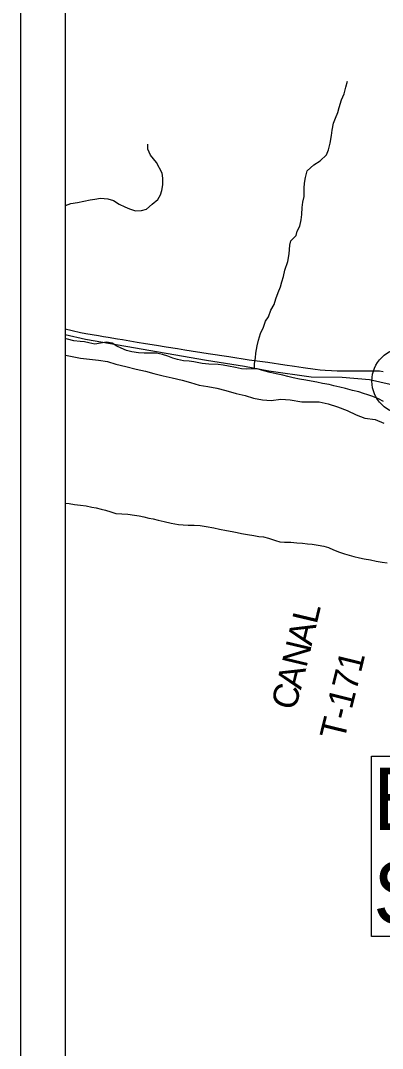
# Model space of a CAD drawing. Extents: x 0 to 34, y 0 to 22.
# Drawn here: x 2.214 to 3.024, y 17.472 to 19.77 of the extents above; entities that cross this region are included whole.
import ezdxf

# ---------------------------------------------------------------- set-up
doc = ezdxf.new("R2010")
doc.units = 0
for name, color, linetype in [('Default', 7, 'Continuous'), ('GM_X_Major_River', 7, 'Continuous'), ('GM_X_Minor_River', 7, 'Continuous'), ('GM_X_Rail_Line', 7, 'Continuous'), ('GM_X_Township_Road_Text', 7, 'Continuous'), ('GM_X_Unincorporated', 7, 'Continuous'), ('GM_X_US_Route', 7, 'Continuous'), ('SH_Cut_Line', 7, 'Continuous'), ('SH_Data', 7, 'Continuous'), ('SH_Text', 7, 'Continuous')]:
    doc.layers.add(name, color=color, linetype=linetype)

msp = doc.modelspace()

# ---------------------------------------------------------------- linework, layer by layer
at = {"layer": 'Default'}
msp.add_lwpolyline([(2.3142, 20.7876), (2.3142, 19.0219), (2.3186, 19.0209), (2.3482, 19.0152), (2.3686, 19.0125), (2.3884, 19.0102), (2.4084, 19.0072), (2.4274, 19.0019), (2.4494, 18.9966), (2.4732, 18.9901), (2.4937, 18.986), (2.5127, 18.981), (2.5335, 18.9753), (2.5532, 18.9712), (2.5756, 18.9658), (2.5945, 18.9605), (2.6138, 18.9548), (2.6328, 18.9514), (2.6532, 18.9476), (2.6733, 18.9427), (2.6968, 18.9359), (2.7165, 18.9317), (2.7355, 18.9252), (2.7556, 18.9215), (2.7749, 18.9203), (2.7961, 18.923), (2.817, 18.9218), (2.8431, 18.9173), (2.8632, 18.9177), (2.8825, 18.9173), (2.9026, 18.9127), (2.9231, 18.9063), (2.9447, 18.8979), (2.9651, 18.8884), (2.9841, 18.8809), (3.0072, 18.8782), (3.0269, 18.8695)], dxfattribs=at)
at = {"layer": 'GM_X_Major_River'}
for points in [[(2.6561, 19.0009), (2.6353, 19.0012), (2.6203, 19.003), (2.6022, 19.007), (2.5916, 19.0083), (2.5788, 19.0093), (2.5656, 19.0121), (2.5547, 19.0153), (2.5434, 19.0193), (2.5314, 19.0233), (2.5182, 19.0261), (2.5076, 19.0263), (2.4906, 19.0258), (2.4777, 19.0271), (2.4634, 19.0292), (2.451, 19.0321), (2.4393, 19.0372), (2.4296, 19.0419), (2.4191, 19.0485), (2.4067, 19.0509), (2.3934, 19.0485), (2.3805, 19.046), (2.3673, 19.0493), (2.3575, 19.0513), (2.3474, 19.0526), (2.3334, 19.0536), (2.3191, 19.0572), (2.3142, 19.0591)], [(3.0264, 18.918), (3.0148, 18.9238), (3.0024, 18.9289), (2.9907, 18.9333), (2.981, 18.9361), (2.9708, 18.94), (2.9569, 18.9429), (2.9414, 18.9473), (2.9283, 18.9502), (2.9151, 18.9534), (2.9049, 18.9558), (2.8894, 18.9587), (2.877, 18.9612), (2.8642, 18.9636), (2.8525, 18.9657), (2.8382, 18.9682), (2.8242, 18.9711), (2.8122, 18.9739), (2.8009, 18.9767), (2.7862, 18.9796), (2.7723, 18.9829), (2.7583, 18.9865), (2.7433, 18.9912), (2.7304, 18.9911), (2.7206, 18.9901), (2.7081, 18.9914), (2.695, 18.9943), (2.6791, 18.9968), (2.6678, 18.9992), (2.6561, 19.0009)], [(2.3142, 18.691), (2.3226, 18.6897), (2.3347, 18.688), (2.3482, 18.6866), (2.3611, 18.6846), (2.3739, 18.6821), (2.3837, 18.68), (2.3946, 18.6776), (2.4044, 18.6748), (2.4164, 18.6712), (2.4277, 18.668), (2.4409, 18.6667), (2.4545, 18.6665), (2.4692, 18.6643), (2.4798, 18.6623), (2.49, 18.6602), (2.5009, 18.6574), (2.5107, 18.6554), (2.522, 18.6529), (2.5355, 18.6497), (2.551, 18.6457), (2.5676, 18.6428), (2.5778, 18.6422), (2.5895, 18.6417), (2.6027, 18.6415), (2.6159, 18.6409), (2.6295, 18.6384), (2.6468, 18.6359), (2.6593, 18.633), (2.6747, 18.6298), (2.6879, 18.6273), (2.6984, 18.6252), (2.7082, 18.6232), (2.7218, 18.6207), (2.7358, 18.6182), (2.7475, 18.6165), (2.7576, 18.6152), (2.7689, 18.6128), (2.7844, 18.6073), (2.7945, 18.6041), (2.8047, 18.6039), (2.8191, 18.6033), (2.8319, 18.6024), (2.8451, 18.601), (2.8564, 18.6001), (2.8662, 18.5992), (2.8802, 18.5971), (2.8926, 18.5946), (2.9032, 18.5918), (2.9144, 18.5863), (2.9276, 18.5812), (2.9389, 18.5776), (2.9494, 18.5744), (2.9599, 18.5716), (2.9724, 18.5684), (2.9829, 18.5663), (2.9972, 18.5638), (3.0097, 18.5614), (3.0229, 18.5589), (3.0342, 18.5572)]]:
    msp.add_lwpolyline(points, dxfattribs=at)
at = {"layer": 'GM_X_Minor_River'}
for points in [[(2.7374, 18.9912), (2.7378, 19.0034), (2.7399, 19.0159), (2.7408, 19.0265), (2.7433, 19.0428), (2.7462, 19.0552), (2.751, 19.0703), (2.7573, 19.0846), (2.7624, 19.0978), (2.7686, 19.1076), (2.7742, 19.1223), (2.7812, 19.1351), (2.7856, 19.1476), (2.7907, 19.1615), (2.7955, 19.1747), (2.7987, 19.1853), (2.8023, 19.1974), (2.8055, 19.2117), (2.8119, 19.2314), (2.8152, 19.2484), (2.8163, 19.2673), (2.8191, 19.2771), (2.8307, 19.2891), (2.8331, 19.2989), (2.8393, 19.3098), (2.8418, 19.3242), (2.8435, 19.3359), (2.8442, 19.3515), (2.8455, 19.3636), (2.8484, 19.3761), (2.8487, 19.395), (2.8492, 19.406), (2.8517, 19.4189), (2.8554, 19.4336), (2.8704, 19.4471), (2.8845, 19.4563), (2.8987, 19.4698), (2.9027, 19.4807), (2.9067, 19.4954), (2.9097, 19.5132), (2.911, 19.5249), (2.9139, 19.5401), (2.9186, 19.5514), (2.9238, 19.5646), (2.927, 19.5752), (2.9325, 19.5925), (2.9381, 19.6057), (2.9421, 19.6212), (2.9453, 19.634)], [(2.3142, 19.356), (2.3151, 19.3563), (2.3265, 19.3606), (2.3414, 19.3634), (2.3558, 19.3659), (2.3702, 19.3687), (2.3805, 19.3708), (2.393, 19.3725), (2.4096, 19.3715), (2.422, 19.3675), (2.4351, 19.359), (2.4472, 19.3535), (2.4577, 19.3487), (2.4712, 19.3447), (2.4845, 19.3449), (2.4963, 19.3485), (2.5086, 19.3593), (2.5216, 19.3701), (2.5275, 19.3803), (2.5299, 19.3901), (2.5324, 19.4026), (2.5326, 19.4174), (2.5309, 19.4284), (2.5181, 19.4525), (2.5047, 19.4686), (2.4993, 19.4824), (2.4991, 19.4938)]]:
    msp.add_lwpolyline(points, dxfattribs=at)
at = {"layer": 'GM_X_Rail_Line'}
msp.add_lwpolyline([(4.6895, 18.1137), (4.6296, 18.1567), (4.5798, 18.1927), (4.4784, 18.2777), (4.364, 18.3544), (4.2732, 18.4099), (4.1565, 18.4748), (4.0563, 18.5278), (3.9136, 18.6104), (3.633, 18.7426), (3.5445, 18.7756), (3.2856, 18.8723), (3.0993, 18.936), (3.041, 18.9562), (2.9951, 18.9667), (2.9337, 18.9715), (2.8642, 18.9726), (2.7699, 18.9856), (2.7152, 18.9964), (2.6303, 19.0094), (2.3595, 19.0564), (2.3142, 19.0671)], dxfattribs=at)
at = {"layer": 'GM_X_Unincorporated'}
msp.add_circle((3.0746, 18.9639), 0.0744, dxfattribs=at)
at = {"layer": 'GM_X_US_Route'}
msp.add_lwpolyline([(2.3142, 19.0806), (2.3295, 19.0767), (2.348, 19.0725), (2.3602, 19.0702), (2.3884, 19.0657), (2.4, 19.0637), (2.4105, 19.0621), (2.4312, 19.0584), (2.4422, 19.0565), (2.4753, 19.051), (2.4937, 19.0479), (2.5183, 19.0439), (2.5397, 19.0405), (2.5655, 19.0364), (2.5815, 19.0338), (2.6342, 19.0255), (2.68, 19.0186), (2.7256, 19.0116), (2.7673, 19.0057), (2.8057, 19), (2.827, 18.9972), (2.8462, 18.9942), (2.8729, 18.9904), (2.8847, 18.989), (2.8959, 18.9879), (2.9098, 18.9871), (2.9222, 18.9867), (2.9427, 18.9867), (2.9564, 18.9867), (2.9974, 18.9868), (3.0079, 18.9867), (3.0172, 18.9863), (3.0252, 18.9854)], dxfattribs=at)
at = {"layer": 'SH_Cut_Line'}
msp.add_lwpolyline([(2.3142, 20.8996), (2.3142, 19.0219), (2.3186, 19.0209), (2.3482, 19.0152), (2.3686, 19.0125), (2.3884, 19.0102), (2.4084, 19.0072), (2.4274, 19.0019), (2.4494, 18.9966), (2.4732, 18.9901), (2.4937, 18.986), (2.5127, 18.981), (2.5335, 18.9753), (2.5532, 18.9712), (2.5756, 18.9658), (2.5945, 18.9605), (2.6138, 18.9548), (2.6328, 18.9514), (2.6532, 18.9476), (2.6733, 18.9427), (2.6968, 18.9359), (2.7165, 18.9317), (2.7355, 18.9252), (2.7556, 18.9215), (2.7749, 18.9203), (2.7961, 18.923), (2.817, 18.9218), (2.8431, 18.9173), (2.8632, 18.9177), (2.8825, 18.9173), (2.9026, 18.9127), (2.9231, 18.9063), (2.9447, 18.8979), (2.9651, 18.8884), (2.9841, 18.8809), (3.0072, 18.8782), (3.0269, 18.8695)], dxfattribs=at)
at = {"layer": 'SH_Data'}
for p, q in [((2.2142, 20.9996), (2.2142, 13.9996)), ((2.3142, 20.8996), (2.3142, 14.0996))]:
    msp.add_line(p, q, dxfattribs=at)
at = {"layer": 'SH_Text'}
msp.add_lwpolyline([(2.9993, 18.1253), (4.4348, 18.1253), (4.4348, 17.7221), (2.9993, 17.7221)], close=True, dxfattribs=at)

# ---------------------------------------------------------------- texts
at = {"layer": 'GM_X_Township_Road_Text'}
for s, height, rotation, p in [('L', 0.0568, 76.6497, (2.8766, 18.4185)), ('A', 0.0568, 76.6493, (2.865, 18.3699)), ('N', 0.0568, 76.6481, (2.8535, 18.3212)), ('T-171', 0.05682, 76.1527, (2.9379, 18.1582)), ('A', 0.0568, 76.0939, (2.8413, 18.2721)), ('C', 0.0568, 73.7785, (2.8276, 18.2249))]:
    msp.add_text(s, height=height, rotation=rotation, dxfattribs=at).set_placement(p)
at = {"layer": 'SH_Text'}
for s, p in [('BEGIN PROJECT', (3.0031, 17.9597)), ('STA. 100+00.00', (3.0031, 17.7497))]:
    msp.add_text(s, height=0.14, dxfattribs=at).set_placement(p)

doc.saveas('drawing.dxf')
